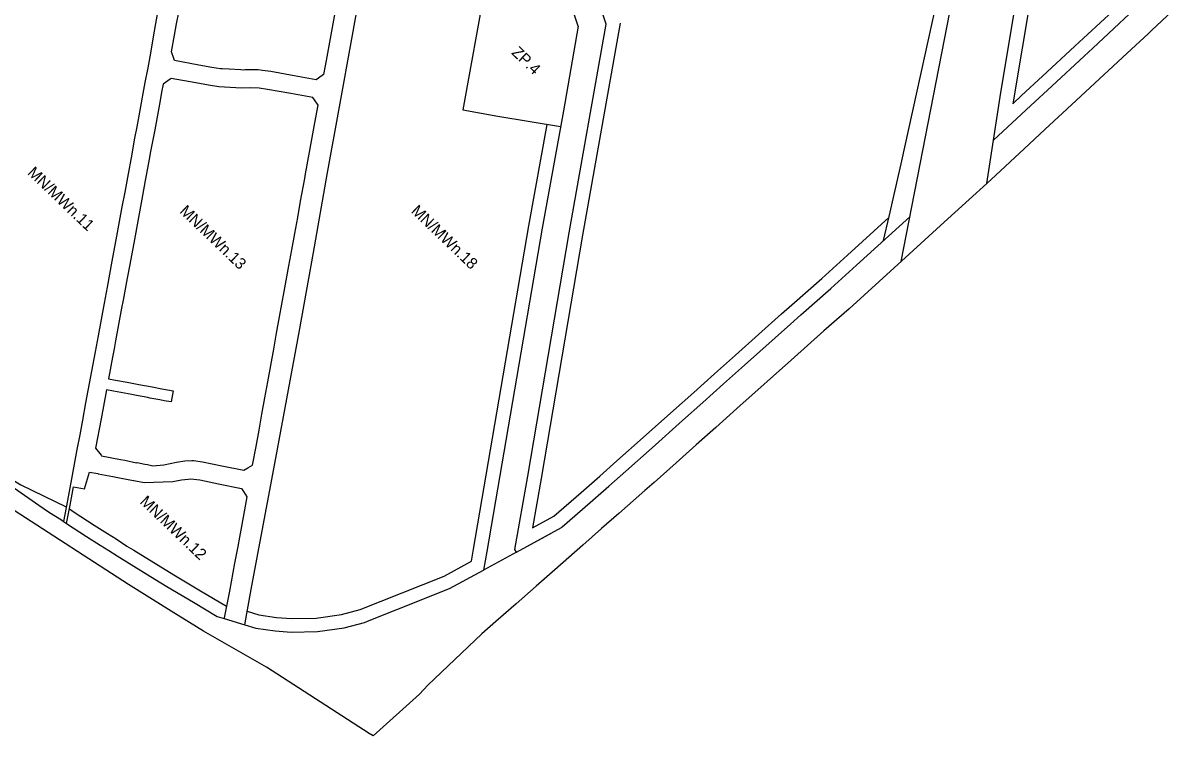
# Model space of a CAD drawing. Extents: x 7420063 to 7422255, y 5550978 to 5552824.
# Drawn here: x 7421664 to 7422172, y 5550978 to 5551293 of the extents above; entities that cross this region are included whole.
import ezdxf

# ---------------------------------------------------------------- set-up
doc = ezdxf.new("R2010")
doc.units = 0
for name, color, linetype in [('linie_rozgraniczajace', 7, 'Continuous'), ('linie_zabudowy_nieprzekraczalne', 7, 'Continuous'), ('oznaczenia_przeznaczen', 7, 'Continuous')]:
    doc.layers.add(name, color=color, linetype=linetype)

msp = doc.modelspace()

# ---------------------------------------------------------------- linework, layer by layer
at = {"layer": 'linie_rozgraniczajace'}
for p, q in [((7421908.66, 5551291.35), (7421896.5, 5551327.67)), ((7421921.01, 5551292.26), (7421908.84, 5551328.6)), ((7422170.72, 5551297.9), (7422161.62, 5551289.43)), ((7422108.35, 5551256.3), (7422117.55, 5551264.84)), ((7422091.85, 5551240.96), (7422108.35, 5551256.3)), ((7422128.33, 5551258.48), (7422114.55, 5551245.68)), ((7422114.55, 5551245.68), (7422105.39, 5551237.17)), ((7422088.9, 5551221.88), (7422081.09, 5551214.77)), ((7422081.09, 5551214.77), (7422068.53, 5551203.32)), ((7422031.47, 5551185.8), (7422055.01, 5551207.23)), ((7422068.53, 5551203.32), (7422054.7, 5551190.72)), ((7422002.38, 5551159.79), (7422006.9, 5551163.83)), ((7422017.05, 5551156.8), (7422004.08, 5551145.22)), ((7421963.66, 5551125.19), (7421972.82, 5551133.37)), ((7421954.74, 5551117.23), (7421963.66, 5551125.19)), ((7421941.31, 5551105.22), (7421954.74, 5551117.23)), ((7421969.39, 5551114.22), (7421960.7, 5551106.46)), ((7421960.7, 5551106.46), (7421951.85, 5551098.55)), ((7421929.69, 5551094.91), (7421941.31, 5551105.22)), ((7421951.85, 5551098.55), (7421942.17, 5551089.89)), ((7421942.17, 5551089.89), (7421938.11, 5551086.33)), ((7421881.51, 5551059.17), (7421901.37, 5551069.98)), ((7421881.51, 5551059.17), (7421897.4, 5551067.82)), ((7421881.51, 5551059.17), (7421866.97, 5551051.22)), ((7421881.51, 5551059.17), (7421880.65, 5551060.27)), ((7421898.32, 5551051.31), (7421890.19, 5551044.14)), ((7421890.19, 5551044.14), (7421881.28, 5551036.3)), ((7421881.28, 5551036.3), (7421872.37, 5551028.47)), ((7421842.28, 5551000.41), (7421838.63, 5550996.38)), ((7421838.63, 5550996.38), (7421818.25, 5550977.96))]:
    msp.add_line(p, q, dxfattribs=at)
for points in [[(7422088.9, 5551221.88), (7422094.81, 5551260.17), (7422102.52, 5551306.4), (7422108.05, 5551341.6), (7422131.71, 5551453), (7422134.47, 5551466.63), (7422139.91, 5551493.55), (7422141.2, 5551499.53), (7422143.52, 5551510.9), (7422145.62, 5551520.79), (7422146.38, 5551524.65)], [(7422051.15, 5551187.49), (7422073.86, 5551303.71), (7422110.29, 5551452.3)], [(7422088.9, 5551221.88), (7422094.81, 5551260.17), (7422102.52, 5551306.4), (7422108.05, 5551341.6)], [(7421761.56, 5551027.07), (7421762.48, 5551032.01), (7421764.74, 5551044.23), (7421775.26, 5551100.59), (7421785.78, 5551156.95), (7421791.84, 5551191.39), (7421797.91, 5551225.83), (7421803.33, 5551255.79), (7421808.75, 5551285.76), (7421811.7, 5551302.02), (7421814.04, 5551315), (7421814.67, 5551318.23), (7421816.91, 5551330.27), (7421810.34, 5551331.48), (7421805.77, 5551332.32), (7421803.85, 5551332.67), (7421797.36, 5551333.86), (7421794.69, 5551334.35), (7421790.87, 5551335.06), (7421784.38, 5551336.26), (7421780.72, 5551336.93), (7421776.58, 5551337.69)], [(7422043.39, 5551196.65), (7422045.82, 5551207.28), (7422051.17, 5551230.56), (7422065.03, 5551293.43), (7422067.2, 5551303.29), (7422067.58, 5551305.01), (7422070.08, 5551316.28)], [(7421867.63, 5551308.95), (7421857.71, 5551254.35), (7421873.22, 5551251.63), (7421900.89, 5551246.97)], [(7421761.56, 5551027.07), (7421762.48, 5551032.01), (7421764.74, 5551044.23), (7421775.26, 5551100.59), (7421785.78, 5551156.95), (7421791.84, 5551191.39), (7421797.91, 5551225.83), (7421803.33, 5551255.79), (7421808.75, 5551285.76), (7421811.7, 5551302.02)], [(7421723.34, 5551299.03), (7421722.23, 5551292.58), (7421721.21, 5551286.63), (7421719.96, 5551279.39), (7421718.77, 5551272.9), (7421717.56, 5551266.4), (7421716.36, 5551259.92), (7421715.15, 5551253.42), (7421713.95, 5551246.92), (7421713, 5551241.83), (7421712.06, 5551236.73), (7421711.7, 5551234.76), (7421709.81, 5551224.59), (7421708.61, 5551218.1), (7421707.4, 5551211.61), (7421706.2, 5551205.12), (7421705, 5551198.62), (7421702.95, 5551187.58), (7421700.82, 5551176.13), (7421699.5, 5551168.97), (7421698.17, 5551161.81), (7421696.84, 5551154.66), (7421695.52, 5551147.5), (7421693.94, 5551139), (7421691.36, 5551125.06), (7421689.96, 5551117.45), (7421688.75, 5551110.96), (7421687.55, 5551104.48), (7421686.25, 5551098.01), (7421686.35, 5551098), (7421685.75, 5551094.75), (7421685.14, 5551091.51), (7421683.38, 5551081.96), (7421681.66, 5551072.7)], [(7421801.32, 5551297.27), (7421800.14, 5551290.78), (7421798.97, 5551284.29), (7421797.79, 5551277.8), (7421797.08, 5551273.88), (7421796.36, 5551269.97), (7421794.1, 5551268.4), (7421793.05, 5551267.67), (7421783.32, 5551269.44), (7421773.06, 5551271.31), (7421769.34, 5551271.81), (7421767.55, 5551272.04), (7421761.82, 5551272.03), (7421760.86, 5551271.98), (7421759.81, 5551272.11), (7421754.64, 5551272.32), (7421751.54, 5551272.5), (7421750.83, 5551272.54), (7421747.07, 5551273.06), (7421741.35, 5551274.12), (7421730.63, 5551276.12), (7421730.3, 5551277.05), (7421729.23, 5551279.95), (7421730.6, 5551287.37), (7421731.52, 5551292.36), (7421732.44, 5551297.34)], [(7422117.55, 5551264.84), (7422131.86, 5551278.15), (7422135.66, 5551281.68), (7422154.21, 5551298.92)], [(7421908.66, 5551291.35), (7421902.16, 5551254.02), (7421892.85, 5551202.21), (7421868.38, 5551059.36), (7421866.97, 5551051.22)], [(7421880.65, 5551060.27), (7421886.49, 5551092.61), (7421904.67, 5551200.14), (7421921.01, 5551292.26)], [(7422161.62, 5551289.43), (7422160.1, 5551288.02), (7422150.81, 5551279.38), (7422132.49, 5551262.35), (7422128.33, 5551258.48)], [(7422105.39, 5551237.17), (7422090.88, 5551223.68), (7422088.9, 5551221.88)], [(7422054.7, 5551190.72), (7422028.17, 5551166.56), (7422017.05, 5551156.8)], [(7422006.9, 5551163.83), (7422020.11, 5551175.46), (7422031.47, 5551185.8)], [(7421972.82, 5551133.37), (7421982.05, 5551141.62), (7422002.38, 5551159.79)], [(7422004.08, 5551145.22), (7421978.64, 5551122.48), (7421969.39, 5551114.22)], [(7421686.02, 5551088.01), (7421690.94, 5551087.1), (7421693.11, 5551094.48), (7421696.71, 5551093.8), (7421696.95, 5551093.74), (7421703.41, 5551092.51), (7421707.11, 5551091.81), (7421712.5, 5551090.78), (7421712.7, 5551090.74), (7421717.19, 5551089.86), (7421729.89, 5551090.25), (7421733.74, 5551091.04), (7421736.67, 5551091.34), (7421737.75, 5551091.45), (7421741.73, 5551091), (7421750, 5551089.32), (7421760.12, 5551087.28), (7421761.03, 5551085.83), (7421762.49, 5551083.5), (7421761.13, 5551076.13), (7421759.94, 5551069.64), (7421759.21, 5551065.66), (7421758.48, 5551061.67), (7421757.11, 5551054.19), (7421754.79, 5551041.87), (7421752.54, 5551030.04), (7421752.43, 5551029.79)], [(7421901.37, 5551069.98), (7421901.65, 5551070.23), (7421913.91, 5551081.01), (7421922.12, 5551088.23), (7421929.69, 5551094.91)], [(7421660.04, 5551087.3), (7421670.76, 5551079.87), (7421675.37, 5551076.68), (7421680.69, 5551073.34), (7421681.66, 5551072.7), (7421683.01, 5551071.82), (7421691.72, 5551066.01), (7421691.79, 5551065.96), (7421697.82, 5551062.23), (7421701.57, 5551059.9), (7421705.23, 5551057.51), (7421706.41, 5551056.74), (7421709.55, 5551054.8), (7421721.94, 5551047.25), (7421727.24, 5551044.02), (7421738.93, 5551036.96), (7421749.39, 5551030.7), (7421752.43, 5551029.79), (7421761.56, 5551027.07), (7421766.43, 5551025.62), (7421774.92, 5551024.3), (7421782.04, 5551023.78), (7421793.6, 5551024.04), (7421805.5, 5551025.76), (7421814.33, 5551028.03), (7421816.46, 5551028.88), (7421828.68, 5551033.77), (7421851.86, 5551043.05)], [(7421683.01, 5551071.82), (7421684.5, 5551079.86), (7421686.02, 5551088.01)], [(7421938.11, 5551086.33), (7421926.66, 5551076.24), (7421919.02, 5551069.52), (7421910.76, 5551062.26), (7421898.32, 5551051.31)], [(7421771.23, 5551008.26), (7421743.43, 5551024.18), (7421729.12, 5551033.11), (7421710.25, 5551044.89), (7421659.87, 5551077.54)], [(7421897.4, 5551067.82), (7421897.4, 5551067.82)], [(7421851.86, 5551043.05), (7421866.97, 5551051.22)], [(7421872.37, 5551028.47), (7421866.14, 5551022.98), (7421842.28, 5551000.41)], [(7421818.25, 5550977.96), (7421816.51, 5550979.08), (7421771.23, 5551008.26)]]:
    msp.add_lwpolyline(points, dxfattribs=at)
msp.add_lwpolyline([(7421793.92, 5551256.47), (7421792.34, 5551258.76), (7421791.61, 5551259.81), (7421781.94, 5551261.56), (7421771.54, 5551263.44), (7421767.93, 5551263.97), (7421764.11, 5551264.18), (7421760.09, 5551264.02), (7421750.17, 5551264.56), (7421745.52, 5551265.23), (7421739.92, 5551266.26), (7421729.18, 5551268.26), (7421728.7, 5551267.93), (7421725.58, 5551265.79), (7421724.9, 5551262.13), (7421724.22, 5551258.48), (7421723.03, 5551252.01), (7421721.84, 5551245.56), (7421719.92, 5551235.28), (7421719.56, 5551233.31), (7421717.68, 5551223.15), (7421716.47, 5551216.65), (7421715.28, 5551210.16), (7421714.07, 5551203.67), (7421712.87, 5551197.18), (7421710.82, 5551186.13), (7421709.69, 5551180.04), (7421707.9, 5551170.36), (7421707.23, 5551166.77), (7421705.9, 5551159.59), (7421704.57, 5551152.41), (7421703.91, 5551148.82), (7421703.24, 5551145.23), (7421701.47, 5551135.66), (7421704.6, 5551135.08), (7421709.71, 5551134.12), (7421714.81, 5551133.17), (7421720.69, 5551132.07), (7421725.01, 5551131.26), (7421729.96, 5551130.33), (7421729.05, 5551125.42), (7421726, 5551125.99), (7421724.1, 5551126.34), (7421719.74, 5551127.15), (7421718.88, 5551127.32), (7421713.89, 5551128.26), (7421711.76, 5551128.65), (7421703.62, 5551130.17), (7421700.55, 5551130.74), (7421698.17, 5551117.92), (7421695.8, 5551105.09), (7421698.22, 5551101.97), (7421698.42, 5551101.71), (7421706.71, 5551100.07), (7421708.74, 5551099.68), (7421713.86, 5551098.6), (7421714.12, 5551098.65), (7421717.48, 5551098.01), (7421718.72, 5551097.74), (7421721.03, 5551097.27), (7421725.87, 5551097.71), (7421731.49, 5551098.79), (7421735.21, 5551099.5), (7421738.18, 5551099.53), (7421738.99, 5551099.53), (7421742.97, 5551099), (7421751.52, 5551097.29), (7421761.17, 5551095.35), (7421762.98, 5551096.37), (7421765.04, 5551097.55), (7421766.56, 5551105.79), (7421767.86, 5551112.93), (7421769.15, 5551120.07), (7421770.45, 5551127.22), (7421771.74, 5551134.37), (7421773.04, 5551141.51), (7421774.35, 5551148.66), (7421775, 5551152.23), (7421775.64, 5551155.79), (7421776.94, 5551162.94), (7421778.99, 5551174.24), (7421781.03, 5551185.49), (7421782.33, 5551192.64), (7421783.62, 5551199.78), (7421784.92, 5551206.93), (7421786.21, 5551214.07), (7421788.05, 5551224.15), (7421788.41, 5551226.12), (7421790.14, 5551235.66), (7421791.32, 5551242.16), (7421792.5, 5551248.65)], close=True, dxfattribs=at)
at = {"layer": 'linie_zabudowy_nieprzekraczalne'}
for p, q in [((7421950.74, 5551121.7), (7421959.66, 5551129.67)), ((7421937.32, 5551109.7), (7421950.74, 5551121.7)), ((7421925.72, 5551099.4), (7421937.32, 5551109.7)), ((7421918.15, 5551092.73), (7421925.72, 5551099.4)), ((7421909.95, 5551085.51), (7421918.15, 5551092.73)), ((7421897.91, 5551074.93), (7421909.95, 5551085.51)), ((7421888.47, 5551069.79), (7421897.91, 5551074.93))]:
    msp.add_line(p, q, dxfattribs=at)
for points in [[(7422113.95, 5551340.51), (7422108.45, 5551305.44), (7422100.38, 5551257.09)], [(7422100.38, 5551257.09), (7422104.27, 5551260.7), (7422113.46, 5551269.24), (7422127.77, 5551282.54), (7422131.57, 5551286.07), (7422150.12, 5551303.32), (7422159.85, 5551312.37), (7422169.05, 5551320.95), (7422172.37, 5551338.2)], [(7421927.19, 5551292.72), (7421910.58, 5551199.12), (7421892.4, 5551091.58), (7421888.47, 5551069.79)], [(7421861.56, 5551055.14), (7421862.47, 5551060.38), (7421886.94, 5551203.24), (7421894.97, 5551247.97)], [(7421959.66, 5551129.66), (7421968.82, 5551137.85), (7421978.05, 5551146.1), (7421998.38, 5551164.26), (7422002.92, 5551168.32), (7422016.11, 5551179.93), (7422027.43, 5551190.24), (7422045.74, 5551206.91)], [(7421625.48, 5551114.93), (7421649.55, 5551096.81), (7421662.74, 5551088.81), (7421682.85, 5551079.1)], [(7421684.2, 5551078.21), (7421686.32, 5551076.83), (7421695.1, 5551070.97), (7421700.98, 5551067.33), (7421704.8, 5551064.96), (7421709.62, 5551061.8), (7421712.69, 5551059.92), (7421730.35, 5551049.15), (7421742.02, 5551042.1), (7421753.52, 5551035.21)], [(7421762.66, 5551033), (7421767.75, 5551031.48), (7421775.6, 5551030.27), (7421782.19, 5551029.78), (7421793.1, 5551030.03), (7421804.32, 5551031.65), (7421812.46, 5551033.75), (7421849.48, 5551048.56), (7421861.56, 5551055.14)]]:
    msp.add_lwpolyline(points, dxfattribs=at)

# ---------------------------------------------------------------- texts
at = {"layer": 'oznaczenia_przeznaczen'}
for s, p in [('ZP.4', (7421878.96, 5551279.3)), ('MN/MWn.11', (7421665.44, 5551226.24)), ('MN/MWn.13', (7421732.51, 5551209.22)), ('MN/MWn.18', (7421834.62, 5551209.3)), ('MN/MWn.12', (7421715, 5551080.98))]:
    msp.add_text(s, height=5, rotation=316.2133, dxfattribs=at).set_placement(p)

doc.saveas('drawing.dxf')
